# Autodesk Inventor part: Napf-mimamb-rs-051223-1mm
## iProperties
Created: 2005-12
Part Number: Napf-mimamb-rs-051223-1mm
Document SubType Name: Modeling
Designer: rsc
Author: rsc
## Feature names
1. Drehung1 [Revolution]
2. Grenzpositionen [Rectangular Pattern]
3. Infinitesimalversatz [Rectangular Pattern]
4. Spiegeln1 [Mirror]
5. Trennen3
6. Trennen4
